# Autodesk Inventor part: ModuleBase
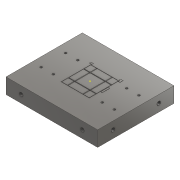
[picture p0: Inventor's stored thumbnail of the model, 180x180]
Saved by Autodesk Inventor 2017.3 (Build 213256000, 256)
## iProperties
Part Number: ModuleBase
Material: ステンレス鋼
Document SubType Name: Modeling
Designer: kyushu-hep
Density: 8 g/cm^3
Appearance: 半つや出し
Mass: 96.9479 g
Surface Area: 172.882 cm^2
Volume: 104.245 cm^3
Author: kyushu-hep
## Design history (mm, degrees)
sketch "スケッチ1"
  geometry: L1 (-60, 50)-(60, 50); L2 (60, 50)-(60, -50); L3 (60, -50)-(-60, -50); L4 (-60, -50)-(-60, 50); 1 further point
  constraints: 8 end point, 2 parallel, 1 horizontal, 1 perpendicular
  dimensions: "d0" = 120 distance of L2.end L3.end; "d1" = 100 distance of L1.end L2.end; "d22" = 50 distance from line of point (0, 0) L3; "d23" = 60 distance from line of L2 point (0, 0)
extrude "押し出し1" new body sketch "スケッチ1" distance "d2" = 20; taper "d3" = 0 deg
sketch "スケッチ4"
  geometry: L1 (17.855, 22.225)-(17.855, 20.225); L2 (17.855, 20.225)-(19.055, 20.225); L3 (19.055, 20.225)-(19.055, 18.225); L4 (19.055, 18.225)-(21.055, 18.225); L5 (21.055, 18.225)-(21.055, 22.225); L6 (21.055, 22.225)-(17.855, 22.225); L7 (21.055, 5)-(21.055, -5); L8 (21.055, -5)-(19.055, -5); L9 (19.055, -5)-(19.055, 5); L10 (19.055, 5)-(21.055, 5); L11 (-60, -50)-(60, -50) reference; L12 (-60, 50)-(-60, -50) reference; L13 (-21.055, 22.225)-(-17.855, 22.225); L14 (-17.855, 22.225)-(-17.855, 20.225); L15 (-17.855, 20.225)-(-21.055, 20.225); L16 (-21.055, 20.225)-(-21.055, 22.225); 1 further point
  constraints: 28 end point, 8 perpendicular, 4 point on line, 2 parallel, 1 collinear, 1 horizontal, 1 vertical
  dimensions: "d12" = 2 distance of L1.start L1.end; "d13" = 1.2 distance of L1.end L2.end; "d14" = 2 distance of L2.end L3.end; "d15" = 2 distance of L3.end L4.end; "d16" = 10 distance of L7.start L7.end; "d24" = 19.055 distance from line of L9 point (0, 0); "d25" = 22.225 distance from line of point (0, 0) L6; "d28" = 17.855 distance from line of point (0, 0) L14
extrude "押し出し4" join sketch "スケッチ4" distance "d29" = 0.3; taper "d30" = 0 deg
sketch "スケッチ6"
  geometry: L1 (20, 20)-(-20, 20); L2 (-20, 20)-(-20, -20); L3 (-20, -20)-(20, -20); L4 (20, -20)-(20, 20); L5 (20, 20)-(-20, -20); L6 (-20, 20)-(20, -20); C1 r 1.5 at (-16, -16); C2 r 1.5 at (-16, 16); C3 r 1.5 at (16, -16); C4 r 1.5 at (16, 16); 1 further point
  constraints: 12 end point, 4 centre point, 2 horizontal, 2 midpoint, 2 parallel, 1 perpendicular, 1 vertical, 6 other
  dimensions: "d41" = 3 diameter of C1; "d42" = 16 horizontal distance of point (0, 0) C1.centre; "d43" = 16 horizontal distance of point (0, 0) C1.centre; "d44" = 40 distance of L3.end L2.end; "d45" = 40 distance of L2.end L1.end; "d48" = 32 distance of C1.centre C2.centre; "d51" = 32 distance of C1.centre C3.centre
sketch "スケッチ7"
  geometry: C1 r 0.5 at (-10, 10); C2 r 0.5 at (10, 10); C3 r 0.5 at (-10, -10); C4 r 0.5 at (10, -10); 1 further point
  constraints: 4 centre point
  dimensions: "d58" = 1 diameter of C1; "d59" = 10 horizontal distance of point (0, 0) C1.centre; "d60" = 10 horizontal distance of point (0, 0) C1.centre; "d61" = 1 diameter of C2; "d62" = 10 horizontal distance of point (0, 0) C2.centre; "d63" = 1 diameter of C3; "d64" = 10 horizontal distance of point (0, 0) C3.centre; "d65" = 1 diameter of C4
extrude "押し出し9" cut sketch "スケッチ7" distance "d66" = 10; taper "d67" = 0 deg
sketch "スケッチ9"
  geometry: L1 (18.5, -19.5)-(-18.5, -19.5); L2 (-18.5, -19.5)-(-18.5, 19.5); L3 (-18.5, 19.5)-(18.5, 19.5); L4 (18.5, 19.5)-(18.5, -19.5); L5 (18.5, -19.5)-(-18.5, 19.5); L6 (-18.5, -19.5)-(18.5, 19.5); L7 (-10.5, 10.5)-(-18, 10.5); L8 (-18, 10.5)-(-18, 19); L9 (-18, 19)-(-10.5, 19); L10 (-10.5, 19)-(-10.5, 10.5); L11 (-10.5, 10.5)-(-18, 19); L12 (-18, 10.5)-(-10.5, 19); L13 (18, 10.5)-(10.5, 10.5); L14 (10.5, 10.5)-(10.5, 19); L15 (10.5, 19)-(18, 19); L16 (18, 19)-(18, 10.5); L17 (-9.5, 19)-(9.5, 19); L18 (9.5, 19)-(9.5, 10.5); L19 (9.5, 10.5)-(-9.5, 10.5); L20 (-9.5, 10.5)-(-9.5, 19); L21 (-18, 9.5)-(-10.5, 9.5); L22 (-10.5, 9.5)-(-10.5, -9.5); L23 (-10.5, -9.5)-(-18, -9.5); L24 (-18, -9.5)-(-18, 9.5); L25 (-18, -10.5)-(-10.5, -10.5); L26 (-10.5, -10.5)-(-10.5, -19); L27 (-10.5, -19)-(-18, -19); L28 (-18, -19)-(-18, -10.5); L29 (-9.5, 9.5)-(9.5, 9.5); L30 (9.5, 9.5)-(9.5, -9.5); L31 (9.5, -9.5)-(-9.5, -9.5); L32 (-9.5, -9.5)-(-9.5, 9.5); L33 (10.5, 9.5)-(18, 9.5); L34 (18, 9.5)-(18, -9.5); L35 (18, -9.5)-(10.5, -9.5); L36 (10.5, -9.5)-(10.5, 9.5); L37 (-9.5, -10.5)-(9.5, -10.5); L38 (9.5, -10.5)-(9.5, -19); L39 (9.5, -19)-(-9.5, -19); L40 (-9.5, -19)-(-9.5, -10.5); L41 (10.5, -10.5)-(18, -10.5); L42 (18, -10.5)-(18, -19); L43 (18, -19)-(10.5, -19); L44 (10.5, -19)-(10.5, -10.5); 2 further points
  constraints: 88 end point, 20 parallel, 19 collinear, 10 horizontal, 10 perpendicular, 4 midpoint, 4 point on line
  dimensions: "d78" = 37 distance of L2.end L3.end; "d79" = 39 distance of L1.end L2.end; "d80" = 7.5 distance of L8.end L9.end; "d81" = 0.5 distance between parallel lines of L3 L9; "d82" = 0.5 distance between parallel lines of L2 L8; "d83" = 8.5 distance of L7.end L8.end; "d88" = 19 distance of L18.end L19.end; "d89" = 8.5 distance of L17.end L18.end; "d90" = 1 distance between parallel lines of L10 L20; "d92" = 19 distance of L21.end L22.end; "d93" = 1 distance between parallel lines of L21 L7; "d94" = 8.5 distance of L25.end L26.end; "d95" = 1 distance between parallel lines of L25 L23; "d96" = 8.5 distance of L13.end L14.end; "d97" = 1 distance between parallel lines of L14 L18
extrude "押し出し11" cut sketch "スケッチ9" distance "d98" = 1; taper "d99" = 0 deg
extrude "押し出し13" cut sketch "スケッチ6" distance "d102" = 10; taper "d103" = 0 deg
sketch "スケッチ10"
  geometry: 1 further point
sketch "スケッチ11"
  geometry: L1 (20, 20)-(-20, 20); L2 (-20, 20)-(-20, -20); L3 (-20, -20)-(20, -20); L4 (20, -20)-(20, 20); L5 (20, 20)-(-20, -20); L6 (-20, 20)-(20, -20); C1 r 1.5 at (-48, -16); C2 r 1.5 at (-48, 16); C3 r 1.5 at (-32, -16); C4 r 1.5 at (-32, 16); C5 r 1.5 at (-16, -16); C6 r 1.5 at (-16, 16); C7 r 1.5 at (0, -16); C8 r 1.5 at (0, 16); C9 r 1.5 at (16, -16); C10 r 1.5 at (16, 16); C11 r 1.5 at (32, -16); C12 r 1.5 at (32, 16); C13 r 1.5 at (48, -16); C14 r 1.5 at (48, 16); 3 further points
  constraints: 14 centre point, 12 end point, 2 horizontal, 2 midpoint, 2 parallel, 1 perpendicular, 1 vertical, 26 other
  dimensions: "d108" = 3 diameter of C1; "d109" = 48 horizontal distance of point (0, 0) C1.centre; "d110" = 16 vertical distance of point (0, 0) C1.centre; "d111" = 40 distance of L3.end L2.end; "d112" = 40 distance of L2.end L1.end; "d113" = 32 distance of C1.centre C2.centre; "d114" = 16 distance of C1.centre C3.centre
extrude "押し出し14" cut sketch "スケッチ11" distance "d115" = 10; taper "d116" = 0 deg
sketch "スケッチ12"
  geometry: C1 r 2.5 at (10, 80); C2 r 2.5 at (10, 20); 1 further point
  constraints: 2 centre point
  dimensions: "d117" = 5 diameter of C1; "d118" = 30 vertical distance of point (0, 50) C1.centre; "d119" = 10 horizontal distance of point (0, 50) C1.centre; "d120" = 5 diameter of C2; "d121" = 30 vertical distance of C2.centre point (0, 50); "d122" = 10 horizontal distance of point (0, 50) C2.centre
extrude "押し出し15" cut sketch "スケッチ12" distance "d123" = 10; taper "d124" = 0 deg
sketch "スケッチ13"
  geometry: C1 r 2.5 at (-10, 20); C2 r 2.5 at (-10, 80); 1 further point
  constraints: 2 centre point
  dimensions: "d125" = 5 diameter of C1; "d126" = 5 diameter of C2; "d127" = 10 horizontal distance of point (0, 50) C1.centre; "d128" = 30 vertical distance of point (0, 50) C1.centre; "d129" = 30 vertical distance of C2.centre point (0, 50); "d130" = 10 horizontal distance of C2.centre point (0, 50)
extrude "押し出し16" cut sketch "スケッチ13" distance "d131" = 10; taper "d132" = 0 deg
sketch "スケッチ14"
  geometry: C1 r 2.5 at (20, 10); C2 r 2.5 at (100, 10); 1 further point
  constraints: 2 centre point
  dimensions: "d133" = 5 diameter of C1; "d134" = 5 diameter of C2; "d135" = 10 vertical distance of point (60, 0) C1.centre; "d136" = 40 horizontal distance of point (60, 0) C1.centre; "d137" = 40 horizontal distance of C2.centre point (60, 0); "d138" = 10 vertical distance of point (60, 0) C2.centre
extrude "押し出し17" cut sketch "スケッチ14" distance "d139" = 10; taper "d140" = 0 deg
sketch "スケッチ15"
  geometry: C1 r 2.5 at (100, -10); C2 r 2.5 at (20, -10); 1 further point
  constraints: 2 centre point
  dimensions: "d141" = 5 diameter of C1; "d142" = 5 diameter of C2; "d143" = 40 horizontal distance of point (60, 0) C1.centre; "d144" = 40 horizontal distance of point (60, 0) C2.centre; "d145" = 10 vertical distance of point (60, 0) C1.centre; "d146" = 10 vertical distance of C2.centre point (60, 0)
extrude "押し出し18" cut sketch "スケッチ15" distance "d147" = 10; taper "d148" = 0 deg
feature "ねじ1" dims "d149" = 10, "d150" = 0
feature "ねじ2" dims "d151" = 10, "d152" = 0
feature "ねじ3" dims "d153" = 10, "d154" = 0
feature "ねじ4" dims "d155" = 10, "d156" = 0
feature "ねじ5" dims "d157" = 10, "d158" = 0
feature "ねじ6" dims "d159" = 10, "d160" = 0
feature "ねじ7" dims "d161" = 10, "d162" = 0
feature "ねじ8" dims "d163" = 10, "d164" = 0
node "ソリッド1"
